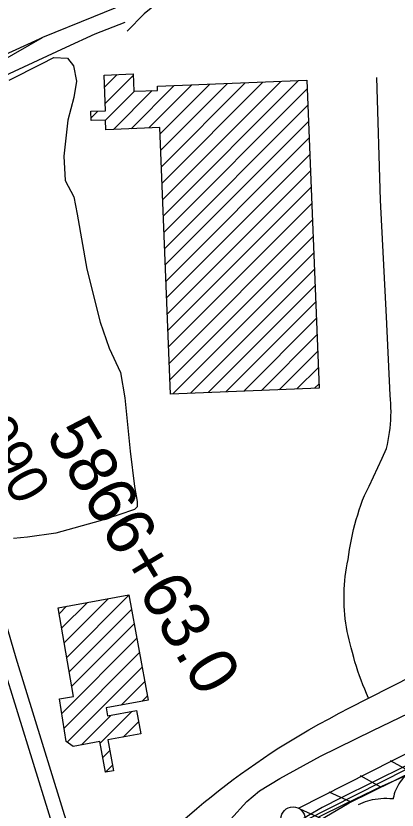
# Model space of a CAD drawing. Extents: x 3598634 to 3636690, y 517270 to 542944.
# Drawn here: x 3609873 to 3610665, y 535647 to 537294 of the extents above; entities that cross this region are included whole.
import ezdxf

# ---------------------------------------------------------------- set-up
doc = ezdxf.new("R2010")
doc.units = 0
for name, color, linetype in [('V-BLDG-OTLN', 7, 'Continuous'), ('V-FLOD-BASE', 7, 'Continuous'), ('V-LEVE-TOET', 7, 'Continuous'), ('V-RAIL-TRAK', 7, 'Continuous'), ('V-RIVR-RANG-IDEN', 7, 'Continuous'), ('V-ROAD-CNTR', 7, 'Continuous'), ('V-RRAP-FSHR', 7, 'Continuous'), ('V-SITE-VEGE', 7, 'Continuous'), ('V-SURV-IDEN', 7, 'Continuous'), ('V-SURV-LINE', 7, 'Continuous'), ('V-TOPO-SHOR', 7, 'Continuous')]:
    doc.layers.add(name, color=color, linetype=linetype)

msp = doc.modelspace()

# ---------------------------------------------------------------- linework, layer by layer
at = {"layer": 'V-BLDG-OTLN'}
for p, q in [((3610057.1, 537146.5), (3610083.3, 537172.7)), ((3610058.5, 537112.5), (3610116.5, 537170.6)), ((3610112.5, 537060.5), (3610201.9, 537149.9)), ((3610149.3, 537062), (3610238.7, 537151.4)), ((3610172.5, 537049.7), (3610275.6, 537152.8)), ((3610173.8, 537015.7), (3610312.4, 537154.3)), ((3610175.2, 536981.7), (3610349.2, 537155.8)), ((3610176.5, 536947.7), (3610386.1, 537157.3)), ((3610177.9, 536913.7), (3610422.9, 537158.7)), ((3610179.3, 536879.7), (3610459.7, 537160.2)), ((3610059.2, 537077.9), (3610119.4, 537138.1)), ((3610075.7, 537059), (3610156.2, 537139.6)), ((3610180.6, 536845.8), (3610478.1, 537143.2)), ((3610182, 536811.8), (3610479.4, 537109.2)), ((3610029.2, 537083.3), (3610043, 537097.1)), ((3610183.3, 536777.8), (3610480.8, 537075.2)), ((3610184.7, 536743.8), (3610482.1, 537041.2)), ((3610186.1, 536709.8), (3610483.5, 537007.2)), ((3610187.4, 536675.8), (3610484.9, 536973.2)), ((3610188.8, 536641.8), (3610486.2, 536939.2)), ((3610190.1, 536607.8), (3610487.6, 536905.2)), ((3610191.5, 536573.8), (3610488.9, 536871.2)), ((3610192.9, 536539.8), (3610490.3, 536837.2)), ((3610198.7, 536510.3), (3610491.7, 536803.3)), ((3610235.5, 536511.8), (3610493, 536769.3)), ((3610272.4, 536513.2), (3610494.4, 536735.3)), ((3610309.2, 536514.7), (3610495.7, 536701.3)), ((3610346, 536516.2), (3610497.1, 536667.3)), ((3610382.8, 536517.7), (3610498.5, 536633.3)), ((3610419.7, 536519.1), (3610499.8, 536599.3)), ((3610456.5, 536520.6), (3610501.2, 536565.3)), ((3610493.3, 536522.1), (3610502.6, 536531.3)), ((3609973.3, 535994.1), (3610065, 536085.7)), ((3609978.6, 535964), (3610107.9, 536093.3)), ((3609962.8, 536054.2), (3609978.5, 536069.9)), ((3609968.1, 536024.2), (3610021.7, 536077.8)), ((3609983.9, 535934), (3610113.3, 536063.4)), ((3609989.2, 535903.9), (3610118.8, 536033.5)), ((3609968.3, 535847.6), (3610124.2, 536003.6)), ((3609973, 535817), (3610129.7, 535973.7)), ((3609979.3, 535787.9), (3610135.1, 535943.8)), ((3610091.8, 535865.1), (3610140.6, 535913.9)), ((3610135.1, 535873), (3610146.1, 535884)), ((3610048, 535785.9), (3610113.6, 535851.6)), ((3610009, 535782.3), (3610070.4, 535843.7)), ((3610096.1, 535798.7), (3610127.9, 535830.5)), ((3610053.4, 535756), (3610067.9, 535770.5)), ((3610058.9, 535726.1), (3610073.4, 535740.5))]:
    msp.add_line(p, q, dxfattribs=at)
for points in [[(3610194.1, 536510.1), (3610171.9, 537062.9), (3610060, 537058.4), (3610059.2, 537078.5), (3610029.5, 537077.3), (3610028.7, 537096.5), (3610059.1, 537097.7), (3610056.1, 537171.6), (3610116.4, 537174), (3610117.8, 537138), (3610167.3, 537140), (3610166.9, 537148.5), (3610477.3, 537160.9), (3610502.9, 536522.5)], [(3610107.8, 536093.5), (3610147.6, 535875.3), (3610060.5, 535859.4), (3610063.6, 535842.4), (3610123.8, 535853.4), (3610132.5, 535805.3), (3610063.8, 535792.8), (3610075.5, 535728.8), (3610059, 535725.8), (3610047.4, 535789.3), (3609991.9, 535779.1), (3609977.3, 535789.3), (3609963.6, 535877.9), (3609992.9, 535882.7), (3609960.6, 536066.7)]]:
    msp.add_lwpolyline(points, close=True, dxfattribs=at)
at = {"layer": 'V-FLOD-BASE'}
msp.add_lwpolyline([(3610829.1, 535812.2), (3610682.9, 535739.2), (3610548.2, 535672.4), (3610508.7, 535652.8), (3610480.8, 535635.9), (3610442.7, 535611.5), (3610412.1, 535588.5), (3610378, 535560.1), (3610264.3, 535459.2)], dxfattribs=at)
at = {"layer": 'V-LEVE-TOET'}
for points in [[(3610318.5, 535627.5), (3610352.5, 535664.8), (3610379.1, 535687.1), (3610421.3, 535712.8), (3610505.6, 535758.8), (3610613.8, 535812.1), (3610726, 535866.1)], [(3610826.5, 535782), (3610633.4, 535697), (3610555.8, 535659.2), (3610501.4, 535632.8)]]:
    msp.add_lwpolyline(points, dxfattribs=at)
at = {"layer": 'V-RAIL-TRAK'}
for points in [[(3610937.8, 537597.3), (3610826.3, 537561.1), (3610683.4, 537516.2), (3610550, 537471.6), (3610397.9, 537423.3), (3610339.4, 537403.9), (3610328, 537400.1), (3610312.9, 537395), (3610288.7, 537385.7), (3610288.1, 537385.4), (3610267.6, 537376.3), (3610243.3, 537364.6), (3610220.4, 537353.4), (3610205.2, 537344.7), (3610194.6, 537338.2), (3610183.1, 537331.3), (3610167.5, 537320.8), (3610153.6, 537310.2), (3610139.7, 537298.8), (3610104, 537263)], [(3610288.1, 537385.4), (3610258.9, 537376.2), (3610228.3, 537365.6), (3610169.8, 537344.5), (3610100.7, 537319.5), (3610033.9, 537292.6), (3609928.4, 537249.4), (3609921.3, 537246.5)], [(3608460.7, 536532.7), (3608628.8, 536614.4), (3608818.3, 536706.1), (3608957.8, 536772.6), (3609114, 536848), (3609175.4, 536877.8), (3609257.7, 536916.6), (3609343.5, 536958.1), (3609441.1, 537005.2), (3609559.7, 537062), (3609658.4, 537109.8), (3609669.9, 537115.3), (3609803.8, 537181.1), (3609840.7, 537199.1), (3609928.4, 537249.4)], [(3609921.3, 537246.5), (3609728.1, 537158.6), (3609540.6, 537070.7), (3609347.4, 536977.2), (3609101.9, 536859.5), (3609053.1, 536836), (3608935.2, 536779.2), (3608809.6, 536718.2), (3608742.7, 536685.7), (3608527.9, 536582.5), (3608272.6, 536460), (3608132.5, 536392.8), (3608062, 536358.2), (3607958.1, 536308.4), (3607754.5, 536210.7), (3607670.8, 536169.9), (3607478.3, 536077.1), (3607353.4, 536016.9), (3607237.7, 535961.5), (3607167.2, 535928.3), (3607022.2, 535858.3), (3606898, 535798.8)]]:
    msp.add_lwpolyline(points, dxfattribs=at)
at = {"layer": 'V-ROAD-CNTR'}
for points in [[(3610605.3, 535879.5), (3610601.2, 535888.7), (3610597.3, 535897.8), (3610593.5, 535907.1), (3610589.9, 535916.4), (3610586.5, 535925.8), (3610583.2, 535935.3), (3610580.1, 535944.8), (3610577.1, 535954.4), (3610574.4, 535964), (3610571.8, 535973.7), (3610569.4, 535983.4), (3610567, 535991.9), (3610564.8, 536000.5), (3610562.8, 536009.1), (3610561, 536017.7), (3610559.4, 536026.4), (3610558, 536035.2), (3610556.9, 536043.9), (3610555.9, 536052.7), (3610555.2, 536061.5), (3610554.7, 536070.3), (3610554.4, 536079.1), (3610554.3, 536088), (3610554.4, 536096.8), (3610554.7, 536105.6), (3610555.2, 536114.5), (3610556, 536123.3), (3610557, 536132), (3610558.1, 536140.8), (3610559.5, 536149.5), (3610561.1, 536158.2), (3610562.9, 536166.9), (3610564.3, 536177.3), (3610565.9, 536187.8), (3610567.7, 536198.2), (3610569.7, 536208.5), (3610571.9, 536218.9), (3610574.3, 536229.2), (3610576.9, 536239.4), (3610579.7, 536249.6), (3610582.7, 536259.7), (3610585.9, 536269.8), (3610589.3, 536279.8), (3610593, 536289.7), (3610596.7, 536299.5), (3610606.3, 536318.8), (3610615.6, 536338.2), (3610624.7, 536357.7), (3610633.6, 536377.2), (3610642.3, 536396.9), (3610644.3, 536405.3), (3610646, 536413.7), (3610647.5, 536422.1), (3610648.8, 536430.6), (3610649.9, 536439.1), (3610650.7, 536447.6), (3610651.3, 536456.2), (3610651.7, 536464.8), (3610651.9, 536473.4), (3610651.8, 536481.9), (3610651.5, 536490.5), (3610651, 536499.1), (3610650.3, 536507.6), (3610642.4, 536670.6), (3610629.8, 536912.3), (3610622.2, 537166.6)], [(3610034.7, 535467.5), (3610003.2, 535543.5), (3609873.5, 535962.3), (3609698.5, 536560.8), (3609585.6, 536936.2), (3609570, 536972.8), (3609539, 536988), (3609507.1, 536986.4), (3609474.6, 536979.1), (3609395.9, 536944.3), (3609204, 536848.1), (3608916.4, 536710.5), (3608844.8, 536677.9)], [(3610007, 535456), (3609974.9, 535533.3), (3609844.8, 535953.7), (3609669.8, 536552.2), (3609557.4, 536926), (3609546.8, 536950.7), (3609532.7, 536957.7), (3609511.2, 536956.6), (3609484, 536950.5), (3609408.7, 536917.1), (3609217.2, 536821.1), (3608929.1, 536683.3), (3608855.6, 536649.8)], [(3610189.6, 535599.8), (3610248.5, 535650.5), (3610263.4, 535662.8), (3610278.4, 535674.9), (3610293.5, 535686.9), (3610308.8, 535698.7), (3610324.2, 535710.3), (3610339.7, 535721.8), (3610355.4, 535733), (3610371.2, 535744.1), (3610387.1, 535755), (3610403.2, 535765.8), (3610419.3, 535776.3), (3610439.9, 535788.8), (3610460.5, 535801.2), (3610481.3, 535813.3), (3610502.2, 535825.1), (3610523.2, 535836.8), (3610544.3, 535848.2), (3610565.6, 535859.4), (3610605.3, 535879.5), (3610698.9, 535927)], [(3610709.4, 535736.4), (3610706.1, 535734.9), (3610702, 535733), (3610698, 535730.7), (3610694, 535728.2), (3610690.2, 535725.5), (3610686.5, 535722.7), (3610683, 535719.6), (3610679.7, 535716.4), (3610676.6, 535712.9), (3610673.6, 535709.3), (3610670.8, 535705.6), (3610668.2, 535701.7), (3610665.9, 535697.7), (3610663.7, 535693.6), (3610661.8, 535689.3), (3610660.1, 535685), (3610658.6, 535680.6), (3610657.4, 535676.1), (3610656.4, 535671.6), (3610656.3, 535670.8)], [(3610584.6, 535658.8), (3610589.2, 535661), (3610593.9, 535663.1), (3610598.7, 535664.9), (3610603.6, 535666.5), (3610608.6, 535667.9), (3610613.6, 535669.1), (3610618.8, 535670.1), (3610624.9, 535670.8), (3610631, 535671.3), (3610637, 535671.6), (3610643.1, 535671.6), (3610649.1, 535671.4), (3610655.2, 535670.9), (3610656.3, 535670.8)]]:
    msp.add_lwpolyline(points, dxfattribs=at)
at = {"layer": 'V-RRAP-FSHR'}
for p, q in [((3610693.9, 535725.7), (3610651.1, 535749.2)), ((3610631, 535694.8), (3610588.3, 535718.3)), ((3610568.1, 535664.1), (3610523.7, 535684.5)), ((3610507.7, 535628.7), (3610463.3, 535649))]:
    msp.add_line(p, q, dxfattribs=at)
for points in [[(3610283.7, 535468.8), (3610304.8, 535469.2), (3610403.3, 535553.5), (3610452.1, 535596.1), (3610565, 535662.3), (3611212.8, 535980.7), (3611755.6, 536243), (3612146.8, 536451.7), (3612655.7, 536703.7), (3613040.1, 536882.2), (3613115.5, 536910.7), (3613121.1, 536940)], [(3610283.7, 535468.8), (3610304.8, 535469.2), (3610403.3, 535553.5), (3610452.1, 535596.1), (3610565, 535662.3), (3611212.8, 535980.7), (3611755.6, 536243), (3611986.4, 536366.1)]]:
    msp.add_lwpolyline(points, dxfattribs=at)
at = {"layer": 'V-SITE-VEGE'}
msp.add_lwpolyline([(3609858.9, 537160.9), (3609926.1, 537195), (3609951.6, 537208.2), (3609980.4, 537206.5), (3609992.6, 537191), (3609999.1, 537159.3), (3609993.5, 537125), (3609981.2, 537078.5), (3609972.6, 537003.7), (3609975.3, 536953.3), (3609993.6, 536919), (3610000.4, 536883.2), (3610020.7, 536769.2), (3610047.8, 536659.3), (3610066.9, 536605.6), (3610090.1, 536554.8), (3610099.6, 536502.5), (3610110.2, 536391.3), (3610119.6, 536318.5), (3610125, 536286.9), (3610125, 536275.9), (3610119.5, 536270.4), (3610086.5, 536259.5), (3610048, 536247.3), (3609955.9, 536221.4), (3609896.9, 536213.4), (3609868, 536210.7)], dxfattribs=at)
at = {"layer": 'V-SURV-LINE'}
for points in [[(3610459.5, 535651.3), (3612525, 536696.9)], [(3612538.6, 536670.2), (3610473, 535624.6)]]:
    msp.add_lwpolyline(points, dxfattribs=at)
msp.add_circle((3610448.4, 535628.9), 25, dxfattribs=at)
at = {"layer": 'V-TOPO-SHOR'}
for points in [[(3609977.5, 537229.7), (3610037.6, 537257.2), (3610099.9, 537281.6)], [(3609613.5, 537059.4), (3609743.2, 537121), (3609977.5, 537229.7)]]:
    msp.add_lwpolyline(points, dxfattribs=at)

# ---------------------------------------------------------------- texts
at = {"layer": 'V-RIVR-RANG-IDEN'}
msp.add_text('U-090', height=83, rotation=299.1293, dxfattribs=at).set_placement((3609728.8, 536539.6))
at = {"layer": 'V-SURV-IDEN'}
msp.add_text('5866+63.0', height=100, rotation=300.6974, dxfattribs=at).set_placement((3609933.8, 536424.5))

doc.saveas('drawing.dxf')
